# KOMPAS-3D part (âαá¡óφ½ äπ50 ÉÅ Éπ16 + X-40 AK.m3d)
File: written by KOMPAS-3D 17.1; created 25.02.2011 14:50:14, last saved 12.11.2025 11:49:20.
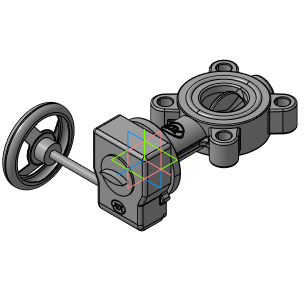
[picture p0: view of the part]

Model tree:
1. Плоскость XY
2. Плоскость ZX
3. Плоскость ZY
4. Ось X
5. Ось Y
6. Ось Z
7. Начало координат
8. Операция без истории:5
